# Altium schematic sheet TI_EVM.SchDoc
size A3; SheetNumber: 1; SheetTotal: 1
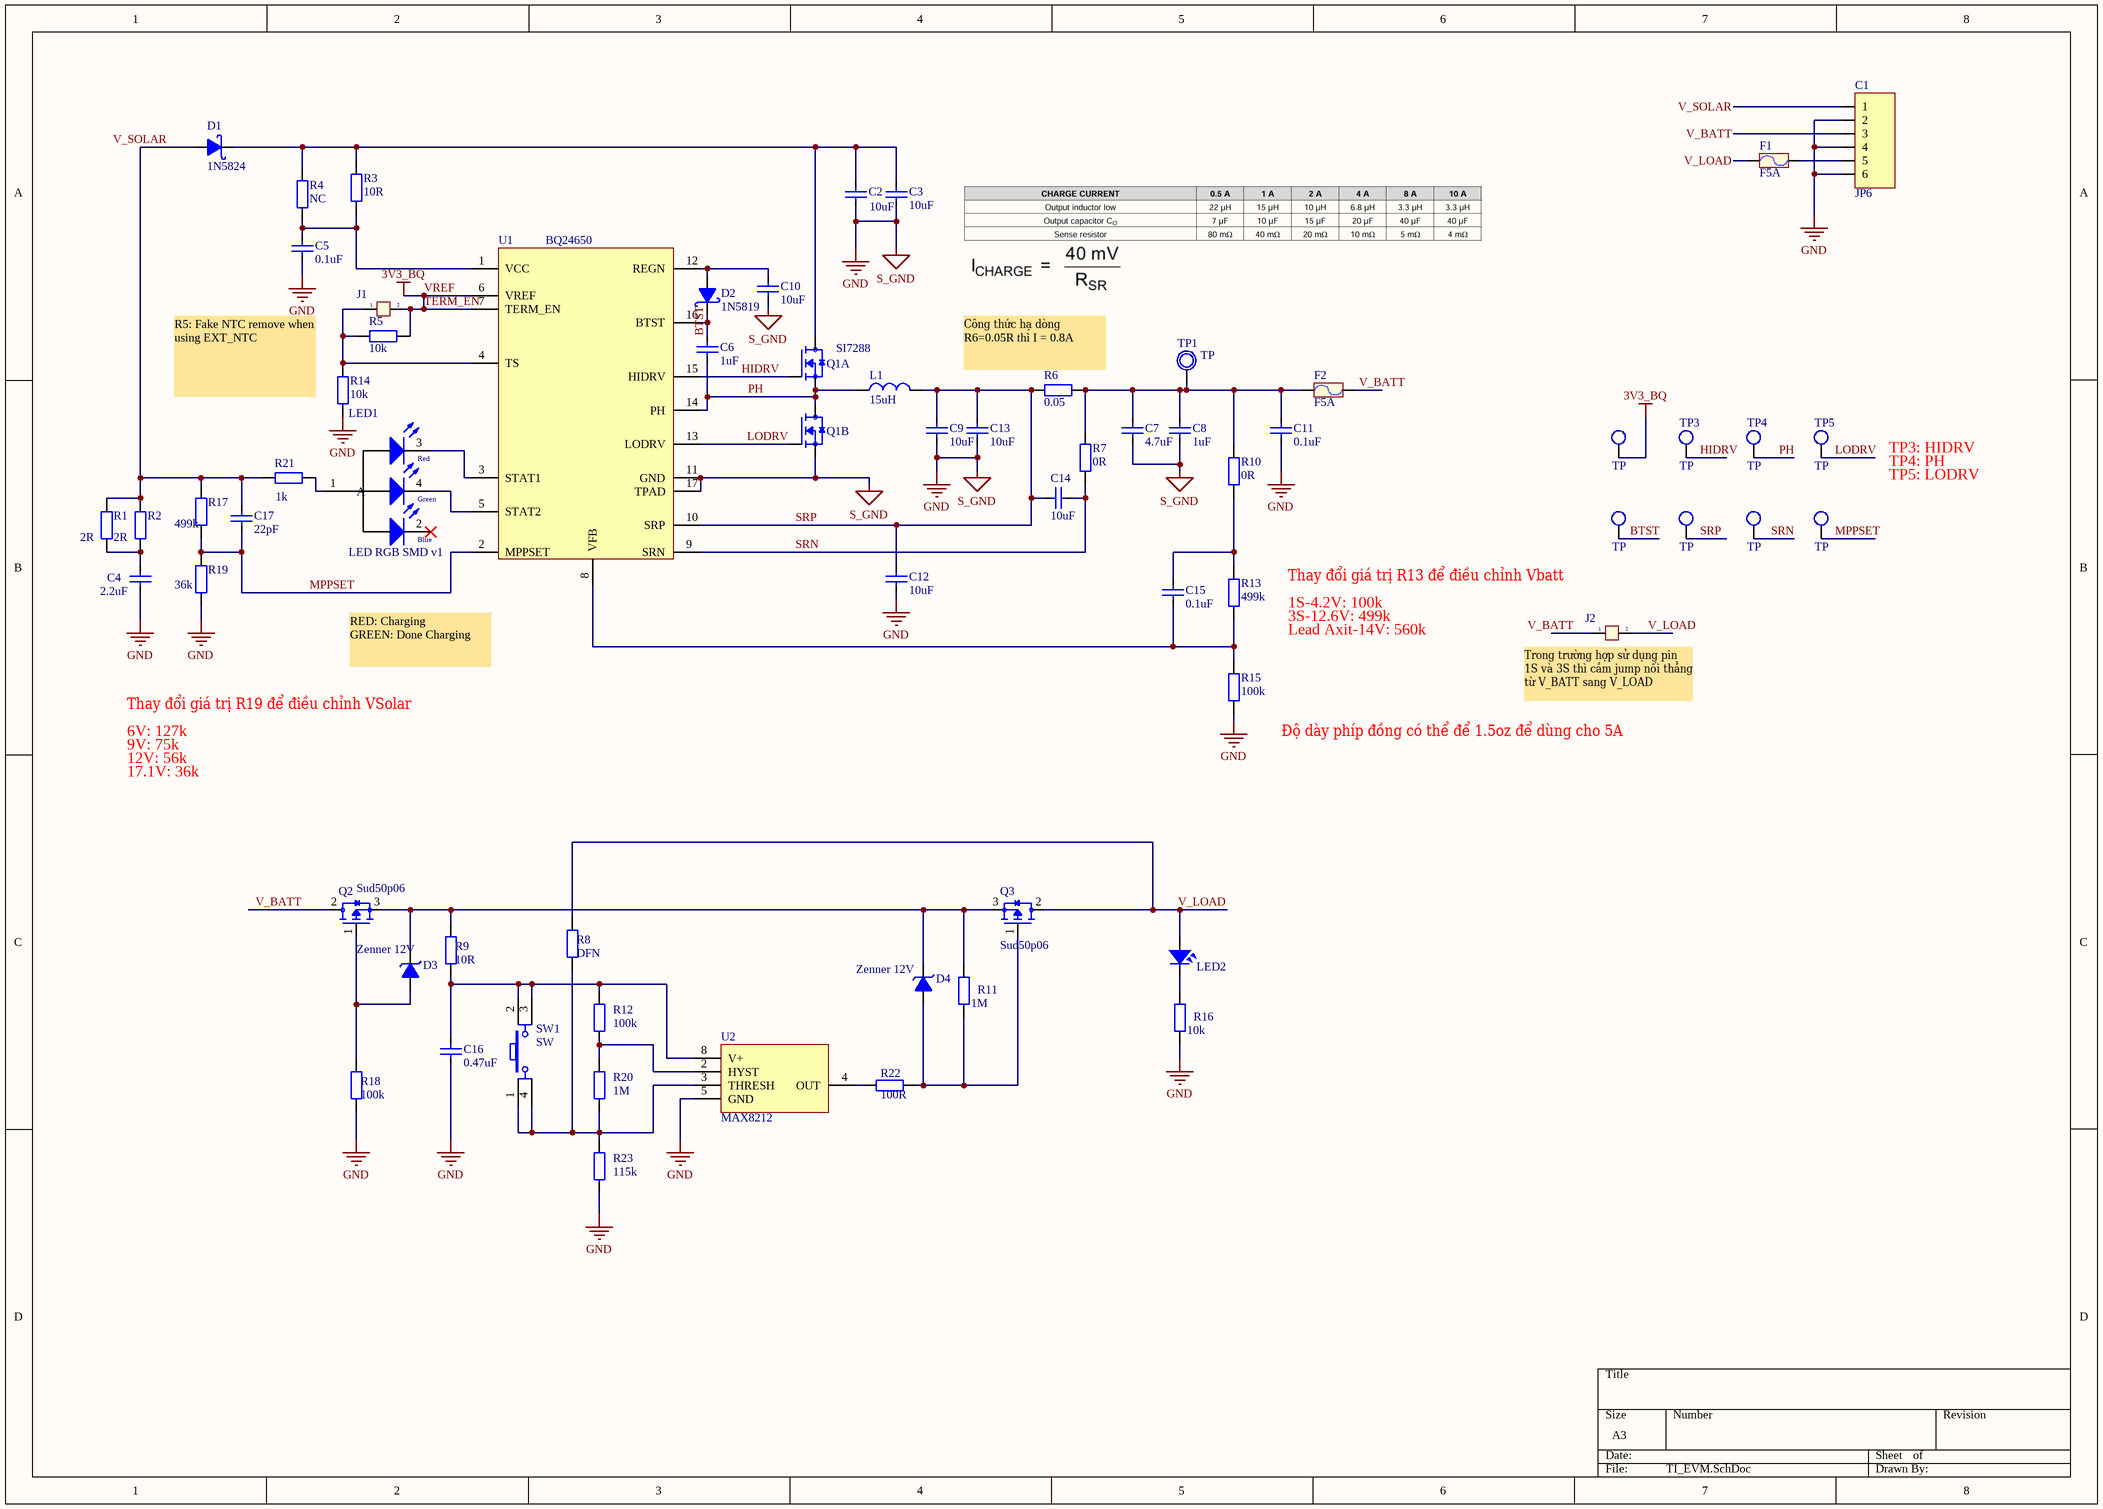
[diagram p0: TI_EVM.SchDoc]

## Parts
C1  JP6  [HB9500-6P]
C2  10uF  [CAP_3216]
C3  10uF  [CAP_3216]
C4  2.2uF  [CAP_0805]
C5  0.1uF  [CAP_0805]
C6  1uF  [CAP_0805]
C7  4.7uF  [CAP_1206]
C8  1uF  [CAP_1206]
C9  10uF  [CAP_1206]
C10  10uF  [CAP_0805]
C11  0.1uF  [CAP_0805]
C12  10uF  [CAP_0805]
C13  10uF  [CAP_1206]
C14  10uF  [CAP_0805]
C15  0.1uF  [CAP_0805]
C16  0.47uF  [CAP_0805]
C17  22pF  [CAP_0805]
D1  1N5824  [SMA]
D2  1N5819  [SMA]
D3  Zenner 12V  [DIODE_ZENER_SMD]
D4  Zenner 12V  [DIODE_ZENER_SMD]
F1  F5A  [RES-SMD-1812]
F2  F5A  [RES-SMD-1812]
J1  Jumper 2  [JP2]  (value not drawn)  (no BOM)
J2  Jumper 2  [JP2]  (value not drawn)  (no BOM)
L1  15uH  [L-SMD-M-12x10]
LED1  LED RGB SMD v1  [LED RGB 3528]
LED2  LED  [LED 3512]  (value not drawn)
Q1  SI7288  [SO-8 dual]  (parts A,B of 2)
Q2  Sud50p06  [TO-252]
Q3  Sud50p06  [TO-252]
R1  2R  [RES-SMD-2512]
R2  2R  [RES-SMD-2512]
R3  10R  [RES-SMD-0805]
R4  NC  [RES-SMD-0805]
R5  10k  [RES-SMD-0805]
R6  0.05  [RES-SMD-2512]
R7  0R  [RES-SMD-0805]
R8  DFN  [RES-SMD-0805]
R9  10R  [RES-SMD-0805]
R10  0R  [RES-SMD-0805]
R11  1M  [RES-SMD-0805]
R12  100k  [RES-SMD-0805]
R13  499k  [RES-SMD-0805]
R14  10k  [RES-SMD-0805]
R15  100k  [RES-SMD-0805]
R16  10k  [RES-SMD-0805]
R17  499k  [RES-SMD-0805]
R18  100k  [RES-SMD-0805]
R19  36k  [RES-SMD-0805]
R20  1M  [RES-SMD-0805]
R21  1k  [RES-SMD-0805]
R22  100R  [RES-SMD-0805]
R23  115k  [RES-SMD-0805]
SW1  SW  [SW4]
TP1  TP  [TP1]  (no BOM)
TP2  TP  [Testpoint 50ml]  (no BOM)
TP3  TP  [Testpoint 50ml]  (no BOM)
TP4  TP  [Testpoint 50ml]  (no BOM)
TP5  TP  [Testpoint 50ml]  (no BOM)
TP6  TP  [Testpoint 50ml]  (no BOM)
TP7  TP  [Testpoint 50ml]  (no BOM)
TP8  TP  [Testpoint 50ml]  (no BOM)
TP9  TP  [Testpoint 50ml]  (no BOM)
U1  BQ24650  [VQFN-16]
U2  MAX8212  [SOIC-8]

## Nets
GND: C1.2 C1.4 C1.6 C2.1 C3.1 C4.1 C5.1 C7.2 C8.2 C9.1 C10.1 C11.1 C12.1 C13.1 C16.1 Q1.3(S2) R14.2 R15.2 R16.2 R18.2 R19.2 R23.2 U1.11(GND) U1.17(TPAD) U2.5(GND)  [also labelled S_GND]
TERM_EN: J1.2 R5.2 TP2.1 U1.6(VREF) U1.7(TERM_EN)  [also labelled 3V3_BQ, VREF]
BTST: C6.2 D2.2(K) TP6.1 U1.16(BTST)
HIDRV: Q1.2(G1) TP3.1 U1.15(HIDRV)
LODRV: Q1.4(G2) TP5.1 U1.13(LODRV)
MPPSET: C17.1 R17.2 R19.1 TP9.1 U1.2(MPPSET)
PH: C6.1 L1.1 Q1.1(S1) Q1.5_6_10(D2) TP4.1 U1.14(PH)
SRN: C14.1 R7.2 TP8.1 U1.9(SRN)
SRP: C9.2 C12.2 C13.2 C14.2 L1.2 R6.2 TP7.1 U1.10(SRP)
V_BATT: C1.3 F2.2 J2.1 Q2.2(D)
V_LOAD: F1.1 J2.2 LED2.1 Q3.2(D) R8.1
V_SOLAR: C1.1 C17.2 D1.1(A) R1.1 R2.1 R17.1 R21.2
NetC1_5: C1.5 F1.2
NetC2_2: C2.2 C3.2 D1.2(K) Q1.7_8_9(D1) R3.1 R4.1
NetC4_2: C4.2 R1.2 R2.2
NetC5_2: C5.2 R3.2 R4.2 U1.1(VCC)
NetC7_1: C7.1 C8.1 C11.2 F2.1 R6.1 R7.1 R10.1 TP1.1
NetC10_2: C10.2 D2.1(A) U1.12(REGN)
NetC15_1: C15.1 R13.2 R15.1 U1.8(VFB)
NetC15_2: C15.2 R10.2 R13.1
NetC16_2: C16.2 R9.2 R12.1 SW1.2 SW1.3 U2.8(V+)
NetD3_1: D3.1(A) Q2.1(G) R18.1
NetD3_2: D3.2(K) D4.2(K) Q2.3(S) Q3.3(S) R9.1 R11.1
NetD4_1: D4.1(A) Q3.1(G) R11.2 R22.2
NetJ1_1: J1.1 R5.1 R14.1 U1.4(TS)
NetLED1_1: LED1.1(A) R21.1
NetLED1_3: LED1.3(C2) U1.3(STAT1)
NetLED1_4: LED1.4(C1) U1.5(STAT2)
NetLED2_2: LED2.2 R16.1
NetR8_2: R8.2 R20.2 R23.1 SW1.1 SW1.4 U2.3(THRESH)
NetR12_2: R12.2 R20.1 U2.2(HYST)
NetR22_1: R22.1 U2.4(OUT)

Not connected (* = marked no-connect by the designer): LED1 2(C3)*

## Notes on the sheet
- (near R6) Công thức hạ dòng R6=0.05R thì I = 0.8A
- (near R14) R5: Fake NTC remove when using EXT_NTC
- TP3: HIDRV
- TP4: PH
- TP5: LODRV
- Thay đổi giá trị R13 để điều chỉnh Vbatt
- 1S-4.2V: 100k
- 3S-12.6V: 499k
- Lead Axit-14V: 560k
- Thay đổi giá trị R19 để điều chỉnh VSolar
- RED: Charging
  GREEN: Done Charging
- (near J2) Trong trường hợp sử dụng pin 1S và 3S thì cắm jump nối thẳng từ V_BATT sang V_LOAD
- 6V: 127k
- 9V: 75k
- 12V: 56k
- 17.1V: 36k
- (near R15) Độ dày phíp đồng có thể để 1.5oz để dùng cho 5A

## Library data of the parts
C1 = JP6: WR-PHD 2.54 mm Angled Socket Header; Manufacturer: W¨¹rth Elektronik eiSos GmbH; partNo: 613006143121; ComponentLink1 Description: Manufacturer; ComponentLink2 Description: Datasheet; NoPins: 06
C2 C3 = CapSMD: Capacitor; Value: 33p
C4-C6 C10-C12 C14-C17 = CapSMD: C_0805; Value: 33p
C7-C9 C13 = CapSMD: C_1206; Value: 33p
D1 = 1N5822: SS54 Diode Schottky 5A 40V; Value: Diode c?m 1N5408
D2 = 1N5822: S4 Diode Schottky 1A 40V; Value: Diode c?m 1N5408
D3 D4 = Zenner: generic zenner diode
F1 F2 = Fuse: Fuse 5A; Designed by: VanDungEvn
J1 J2 = JP 2: Value: JP 2
L1 = Inductor: Value: 150 mH
LED2 = LED SMD: Value: LED 3 - 5 ly 2 Colour
Q1 = Dual MOSFET-N
Q2 Q3 = MOSFET-P
R1 R2 R6 = Resistor - SMD: R_2512; Manufacturer: Generic Components; Class: Passive
R3-R5 R7-R23 = Resistor - SMD: R_0805; Manufacturer: Generic Components; Class: Passive
SW1 = SW4: Switch button 4 pin; Value: Button chip 4 pin
TP1 = TP1: Test Point
TP2-TP9 = TP_1: Test Point
U1 = BQ24650: BQ24650 Stand-Alone Synchronous Buck Battery Charge Controller for Solar Power / With Maximum Power Point Tracking
U2 = MAX8212: Microprocessor Voltage Monitors / with Programmable Voltage Detection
